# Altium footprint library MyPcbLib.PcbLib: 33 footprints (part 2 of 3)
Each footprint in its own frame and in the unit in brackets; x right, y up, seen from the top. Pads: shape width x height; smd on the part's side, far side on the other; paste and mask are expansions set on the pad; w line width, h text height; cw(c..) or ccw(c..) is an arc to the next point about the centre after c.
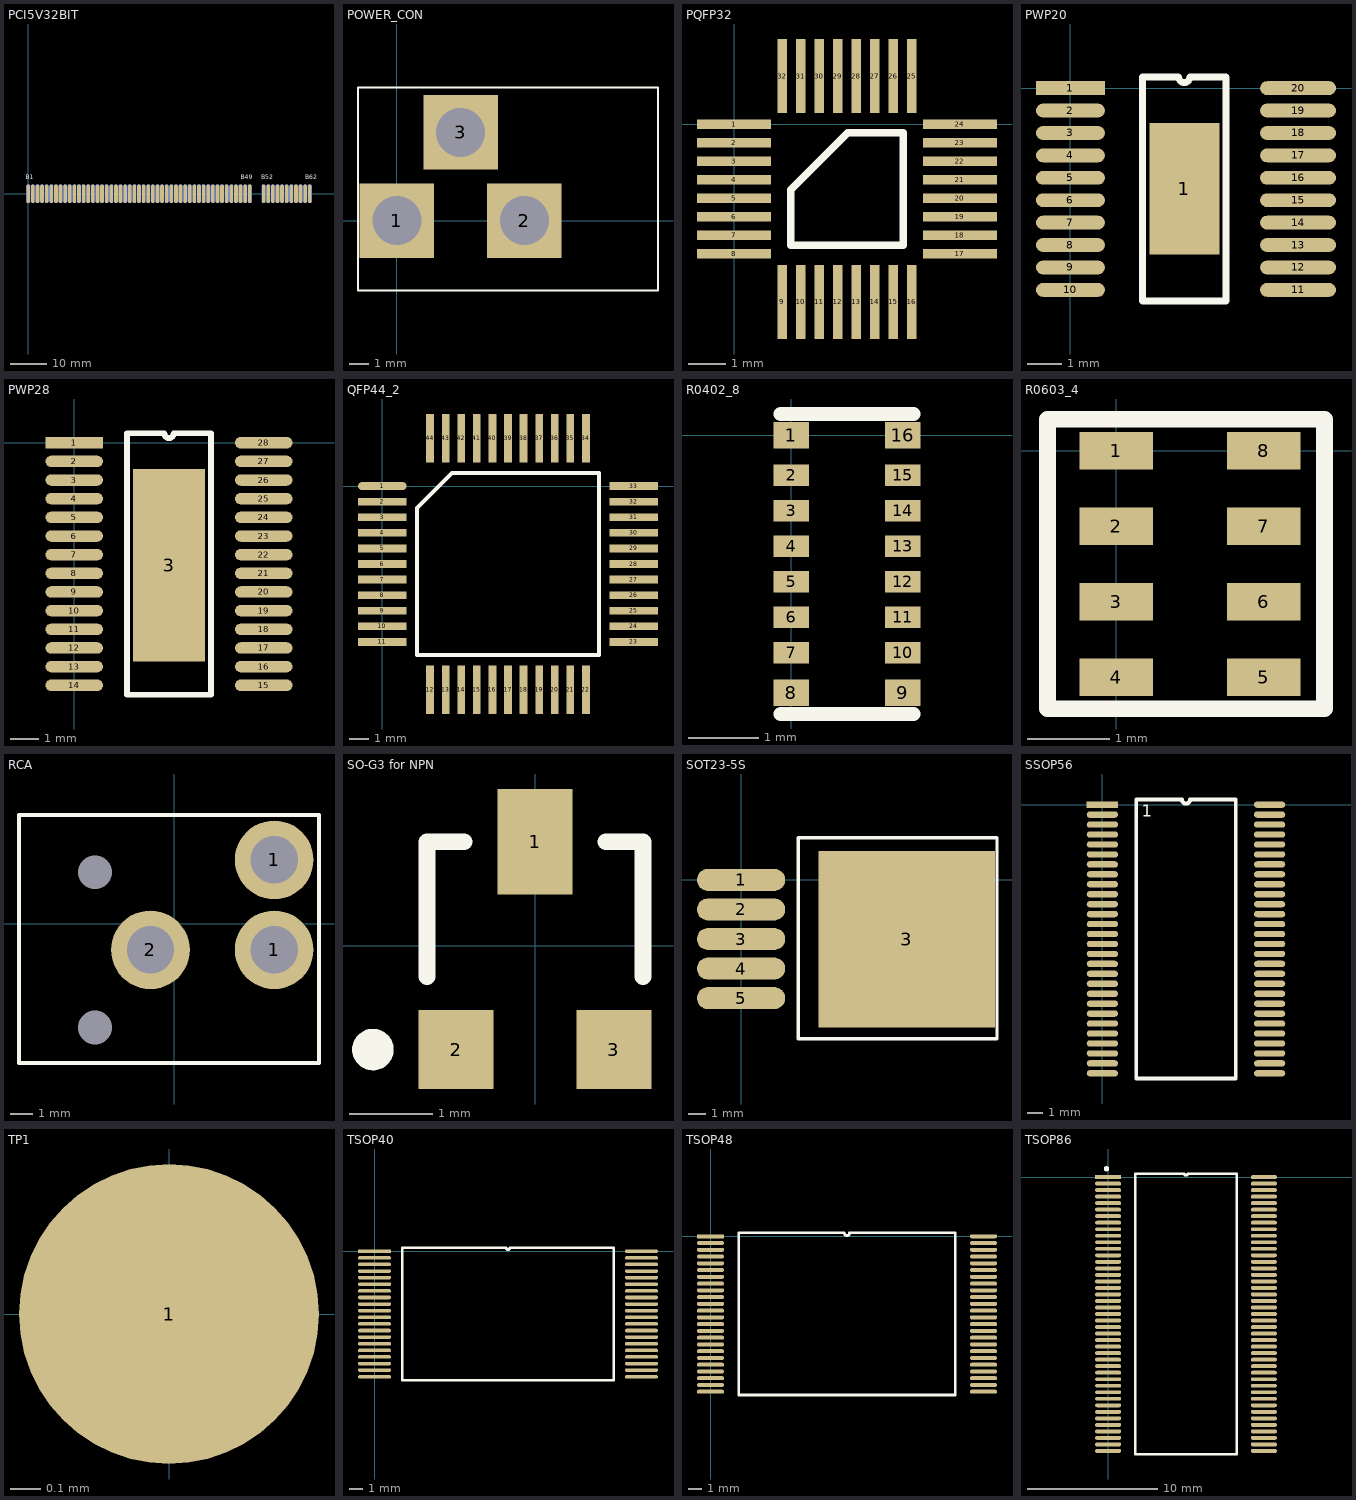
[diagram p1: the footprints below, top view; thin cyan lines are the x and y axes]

## PCI5V32BIT [mil]
pads (120):
  oval 40x200 smd far side: A1(0,0) A2(50,0) A3(100,0) A4(150,0) A5(200,0) A6(250,0) A7(300,0) A8(350,0) A9(400,0) A10(450,0) A11(500,0) A12(550,0) A13(600,0) A14(650,0) A15(700,0) A16(750,0) A17(800,0) A18(850,0) A19(900,0) A20(950,0) A21(1000,0) A22(1050,0) A23(1100,0) A24(1150,0) A25(1200,0) A26(1250,0) A27(1300,0) A28(1350,0) A29(1400,0) A30(1450,0) A31(1500,0) A32(1550,0) A33(1600,0) A34(1650,0) A35(1700,0) A36(1750,0) A37(1800,0) A38(1850,0) A39(1900,0) A40(1950,0) A41(2000,0) A42(2050,0) A43(2100,0) A44(2150,0) A45(2200,0) A46(2250,0) A47(2300,0) A48(2350,0) A49(2400,0) A52(2550,0) A53(2600,0) A54(2650,0) A55(2700,0) A56(2750,0) A57(2800,0) A58(2850,0) A59(2900,0) A60(2950,0) A61(3000,0) A62(3050,0)
  oval 40x200 smd: B1(0,0) B2(50,0) B3(100,0) B4(150,0) B5(200,0) B6(250,0) B7(300,0) B8(350,0) B9(400,0) B10(450,0) B11(500,0) B12(550,0) B13(600,0) B14(650,0) B15(700,0) B16(750,0) B17(800,0) B18(850,0) B19(900,0) B20(950,0) B21(1000,0) B22(1050,0) B23(1100,0) B24(1150,0) B25(1200,0) B26(1250,0) B27(1300,0) B28(1350,0) B29(1400,0) B30(1450,0) B31(1500,0) B32(1550,0) B33(1600,0) B34(1650,0) B35(1700,0) B36(1750,0) B37(1800,0) B38(1850,0) B39(1900,0) B40(1950,0) B41(2000,0) B42(2050,0) B43(2100,0) B44(2150,0) B45(2200,0) B46(2250,0) B47(2300,0) B48(2350,0) B49(2400,0) B52(2550,0) B53(2600,0) B54(2650,0) B55(2700,0) B56(2750,0) B57(2800,0) B58(2850,0) B59(2900,0) B60(2950,0) B61(3000,0) B62(3050,0)
Top Overlay:
  text "B1" at -25,155 h48
  text "B49" at 2300,155 h48
  text "B52" at 2525,155 h48
  text "B62" at 3000,155 h48
Bottom Overlay:
  text "A11" at 525,155 h48
  text "A62" at 3125,155 h48
  text "A14" at 725,155 h48
  text "A1" at 25,155 h48

## POWER_CON [mm] "for power input"
pads (3):
  rect 3.8x3.8 hole 2.5: 1(0,0) 2(6.5,0) 3(3.25,4.5)
Top Overlay:
  lines w0.102: -1.981,-3.556 -1.981,6.782 13.31,6.782 13.31,-3.556 -1.981,-3.556

## PQFP32 [mm] "PQFP32;for TVP5150A"
height 1.05
pads (32):
  rect 2x0.25 smd: 1(0,0) 2(0,-0.5) 3(0,-1) 4(0,-1.5) 5(0,-2) 6(0,-2.5) 7(0,-3) 8(0,-3.5) 17(6.1,-3.5) 18(6.1,-3) 19(6.1,-2.5) 20(6.1,-2) 21(6.1,-1.5) 22(6.1,-1) 23(6.1,-0.5) 24(6.1,0)
  rect 0.25x2 smd: 9(1.3,-4.8) 10(1.8,-4.8) 11(2.3,-4.8) 12(2.8,-4.8) 13(3.3,-4.8) 14(3.8,-4.8) 15(4.3,-4.8) 16(4.8,-4.8) 25(4.8,1.3) 26(4.3,1.3) 27(3.8,1.3) 28(3.3,1.3) 29(2.8,1.3) 30(2.3,1.3) 31(1.8,1.3) 32(1.3,1.3)
Top Overlay:
  lines w0.2: 1.535,-3.265 4.565,-3.265 4.565,-0.235 3.07,-0.235 1.535,-1.77 1.535,-3.265

## PWP20 [mm] "PWP20;PSO;PWP (R-PDSO-G**);for TPS54310"
pads (21):
  rect 2x0.4 smd: 1(0,0)
  rect 2.032x3.81 smd: 1(3.302,-2.921)
  oval 2x0.4 smd: 2(0,-0.65) 3(0,-1.3) 4(0,-1.95) 5(0,-2.6) 6(0,-3.25) 7(0,-3.9) 8(0,-4.55) 9(0,-5.2) 10(0,-5.85)
  oval 2.2x0.4 smd: 11(6.6,-5.85) 12(6.6,-5.2) 13(6.6,-4.55) 14(6.6,-3.9) 15(6.6,-3.25) 16(6.6,-2.6) 17(6.6,-1.95) 18(6.6,-1.3) 19(6.6,-0.65) 20(6.6,0)
Top Overlay:
  lines w0.2: 2.085,-6.175 4.515,-6.175 4.515,0.325 3.462,0.325 cw(c3.3,0.325) 3.137,0.325 2.085,0.325 2.085,-6.175
Top Paste:
  rectangle: 2.286,-4.318 4.318,-1.524

## PWP28 [mm] "PWP28;for TPS767D318"
pads (29):
  rect 2x0.4 smd: 1(0,0)
  oval 2x0.4 smd: 2(0,-0.65) 3(0,-1.3) 4(0,-1.95) 5(0,-2.6) 6(0,-3.25) 7(0,-3.9) 8(0,-4.55) 9(0,-5.2) 10(0,-5.85) 11(0,-6.5) 12(0,-7.15) 13(0,-7.8) 14(0,-8.45) 15(6.6,-8.45) 16(6.6,-7.8) 17(6.6,-7.15) 18(6.6,-6.5) 19(6.6,-5.85) 20(6.6,-5.2) 21(6.6,-4.55) 22(6.6,-3.9) 23(6.6,-3.25) 24(6.6,-2.6) 25(6.6,-1.95) 26(6.6,-1.3) 27(6.6,-0.65) 28(6.6,0)
  rect 2.5x6.7 smd: 3(3.302,-4.267)
Top Overlay:
  lines w0.2: 1.835,-8.775 1.835,0.325 3.137,0.325 ccw(c3.3,0.325) 3.462,0.325 4.765,0.325 4.765,-8.775 1.835,-8.775

## QFP44_2 [mm]
pads (44):
  oval 2.5x0.4 smd: 1(0,0)
  rect 2.5x0.4 smd: 2(0,-0.8) 3(0,-1.6) 4(0,-2.4) 5(0,-3.2) 6(0,-4) 7(0,-4.8) 8(0,-5.6) 9(0,-6.4) 10(0,-7.2) 11(0,-8) 23(12.9,-8) 24(12.9,-7.2) 25(12.9,-6.4) 26(12.9,-5.6) 27(12.9,-4.8) 28(12.9,-4) 29(12.9,-3.2) 30(12.9,-2.4) 31(12.9,-1.6) 32(12.9,-0.8) 33(12.9,0)
  rect 0.4x2.5 smd: 12(2.45,-10.45) 13(3.25,-10.45) 14(4.05,-10.45) 15(4.85,-10.45) 16(5.65,-10.45) 17(6.45,-10.45) 18(7.25,-10.45) 19(8.05,-10.45) 20(8.85,-10.45) 21(9.65,-10.45) 22(10.45,-10.45) 34(10.45,2.45) 35(9.65,2.45) 36(8.85,2.45) 37(8.05,2.45) 38(7.25,2.45) 39(6.45,2.45) 40(5.65,2.45) 41(4.85,2.45) 42(4.05,2.45) 43(3.25,2.45) 44(2.45,2.45)
Top Overlay:
  lines w0.2: 1.785,-8.665 11.115,-8.665 11.115,0.665 3.57,0.665 1.785,-1.12 1.785,-8.665

## R0402_8 [mil]
pads (16):
  rect 20x15 smd: 1(0,0) 8(0,-145) 9(63,-145) 16(63,0)
  rect 20x12 smd: 2(0,-22.5) 3(0,-42.5) 4(0,-62.5) 5(0,-82.5) 6(0,-102.5) 7(0,-122.5) 10(63,-122.5) 11(63,-102.5) 12(63,-82.5) 13(63,-62.5) 14(63,-42.5) 15(63,-22.5)
Top Overlay:
  lines w8: -5.8,-157 69,-157 ; -5.8,12 69,12

## R0603_4 [mil] "for ResPackX4____OK!"
pads (8):
  rect 35x18 smd: 1(0,0) 2(0,-36) 3(0,-72) 4(0,-108) 5(70.16,-108) 6(70.16,-72) 7(70.16,-36) 8(70.16,0)
Top Overlay:
  lines w8: -32.84,15 -32.84,-123 99.16,-123 99.16,15 -31.84,15

## RCA [mm]
pads (5):
  round 3.5 hole 2.1: 1(4.433,-1.168) 1(4.433,2.832) 2(-1.067,-1.168)
  round 0 hole 1.5: 3(-3.53,2.282) 4(-3.53,-4.618)
Top Overlay:
  lines w0.2: -6.909,-6.198 6.426,-6.198 6.426,4.826 -6.909,4.826 -6.909,-6.198

## SO-G3 for NPN [mm]
pads (3):
  rect 0.9x1.27 smd: 1(0,1.25)
  rect 0.9x0.95 smd: 2(-0.95,-1.25) 3(0.95,-1.25)
Top Overlay:
  circle w0.25: c-1.95,-1.25 r0.125
  lines w0.2: -1.3,-0.375 -1.3,1.25 -0.85,1.25 ; 0.85,1.25 1.3,1.25 1.3,-0.375

## SOT23-5S [mil] "for TPS75733"
pads (6):
  oval 200x50 smd: 1(0,0) 2(0,-67) 3(0,-134) 4(0,-201) 5(0,-268)
  rect 400x400 smd: 3(375,-135)
Top Overlay:
  lines w7.87: 130,-360 130,95 580,95 580,-360 130,-360

## SSOP56 [mm] "SSOP56;for CYC68013"
pads (56):
  rect 2x0.4 smd: 1(0,0)
  oval 2x0.4 smd: 2(0,-0.635) 3(0,-1.27) 4(0,-1.905) 5(0,-2.54) 6(0,-3.175) 7(0,-3.81) 8(0,-4.445) 9(0,-5.08) 10(0,-5.715) 11(0,-6.35) 12(0,-6.985) 13(0,-7.62) 14(0,-8.255) 15(0,-8.89) 16(0,-9.525) 17(0,-10.16) 18(0,-10.795) 19(0,-11.43) 20(0,-12.065) 21(0,-12.7) 22(0,-13.335) 23(0,-13.97) 24(0,-14.605) 25(0,-15.24) 26(0,-15.875) 27(0,-16.51) 28(0,-17.145) 29(10.668,-17.145) 30(10.668,-16.51) 31(10.668,-15.875) 32(10.668,-15.24) 33(10.668,-14.605) 34(10.668,-13.97) 35(10.668,-13.335) 36(10.668,-12.7) 37(10.668,-12.065) 38(10.668,-11.43) 39(10.668,-10.795) 40(10.668,-10.16) 41(10.668,-9.525) 42(10.668,-8.89) 43(10.668,-8.255) 44(10.668,-7.62) 45(10.668,-6.985) 46(10.668,-6.35) 47(10.668,-5.715) 48(10.668,-5.08) 49(10.668,-4.445) 50(10.668,-3.81) 51(10.668,-3.175) 52(10.668,-2.54) 53(10.668,-1.905) 54(10.668,-1.27) 55(10.668,-0.635) 56(10.668,0)
Top Overlay:
  lines w0.254: 2.159,-17.462 2.159,0.318 5.08,0.318 ccw(c5.334,0.318) 5.588,0.317 8.509,0.318 8.509,-17.462 2.159,-17.462
  text "1" at 2.515,-0.762 h0.76

## TP1 [mm]
pads (1):
  round 1 smd: 1(0,0)

## TSOP40 [mm] "TSOP40;for Am29LV033C"
height 1.2
pads (40):
  rect 2.5x0.27 smd: 1(0,0)
  oval 2.5x0.27 smd: 2(0,-0.5) 3(0,-1) 4(0,-1.5) 5(0,-2) 6(0,-2.5) 7(0,-3) 8(0,-3.5) 9(0,-4) 10(0,-4.5) 11(0,-5) 12(0,-5.5) 13(0,-6) 14(0,-6.5) 15(0,-7) 16(0,-7.5) 17(0,-8) 18(0,-8.5) 19(0,-9) 20(0,-9.5) 21(20.2,-9.5) 22(20.2,-9) 23(20.2,-8.5) 24(20.2,-8) 25(20.2,-7.5) 26(20.2,-7) 27(20.2,-6.5) 28(20.2,-6) 29(20.2,-5.5) 30(20.2,-5) 31(20.2,-4.5) 32(20.2,-4) 33(20.2,-3.5) 34(20.2,-3) 35(20.2,-2.5) 36(20.2,-2) 37(20.2,-1.5) 38(20.2,-1) 39(20.2,-0.5) 40(20.2,0)
Top Overlay:
  lines w0.2: 2.085,-9.75 18.115,-9.75 18.115,0.25 10.225,0.25 cw(c10.1,0.25) 9.975,0.25 2.085,0.25 2.085,-9.75

## TSOP48 [mm] "for Am29LV800B"
pads (48):
  rect 2x0.3 smd: 1(0,0)
  oval 2x0.3 smd: 2(0,-0.5) 3(0,-1) 4(0,-1.5) 5(0,-2) 6(0,-2.5) 7(0,-3) 8(0,-3.5) 9(0,-4) 10(0,-4.5) 11(0,-5) 12(0,-5.5) 13(0,-6) 14(0,-6.5) 15(0,-7) 16(0,-7.5) 17(0,-8) 18(0,-8.5) 19(0,-9) 20(0,-9.5) 21(0,-10) 22(0,-10.5) 23(0,-11) 24(0,-11.5) 25(20.2,-11.5) 26(20.2,-11) 27(20.2,-10.5) 28(20.2,-10) 29(20.2,-9.5) 30(20.2,-9) 31(20.2,-8.5) 32(20.2,-8) 33(20.2,-7.5) 34(20.2,-7) 35(20.2,-6.5) 36(20.2,-6) 37(20.2,-5.5) 38(20.2,-5) 39(20.2,-4.5) 40(20.2,-4) 41(20.2,-3.5) 42(20.2,-3) 43(20.2,-2.5) 44(20.2,-2) 45(20.2,-1.5) 46(20.2,-1) 47(20.2,-0.5) 48(20.2,0)
Top Overlay:
  lines w0.2: 9.9,0.25 ccw(c10.1,0.25) 10.3,0.25 ; 9.906,0.254 2.085,0.25 2.085,-11.75 18.115,-11.75 18.115,0.25 10.287,0.254

## TSOP86 [mm] "TSOP;43*2;for HY57V283220"
pads (86):
  rect 2x0.3 smd: 1(0,0)
  oval 2x0.3 smd: 2(0,-0.5) 3(0,-1) 4(0,-1.5) 5(0,-2) 6(0,-2.5) 7(0,-3) 8(0,-3.5) 9(0,-4) 10(0,-4.5) 11(0,-5) 12(0,-5.5) 13(0,-6) 14(0,-6.5) 15(0,-7) 16(0,-7.5) 17(0,-8) 18(0,-8.5) 19(0,-9) 20(0,-9.5) 21(0,-10) 22(0,-10.5) 23(0,-11) 24(0,-11.5) 25(0,-12) 26(0,-12.5) 27(0,-13) 28(0,-13.5) 29(0,-14) 30(0,-14.5) 31(0,-15) 32(0,-15.5) 33(0,-16) 34(0,-16.5) 35(0,-17) 36(0,-17.5) 37(0,-18) 38(0,-18.5) 39(0,-19) 40(0,-19.5) 41(0,-20) 42(0,-20.5) 43(0,-21) 44(11.938,-21) 45(11.938,-20.5) 46(11.938,-20) 47(11.938,-19.5) 48(11.938,-19) 49(11.938,-18.5) 50(11.938,-18) 51(11.938,-17.5) 52(11.938,-17) 53(11.938,-16.5) 54(11.938,-16) 55(11.938,-15.5) 56(11.938,-15) 57(11.938,-14.5) 58(11.938,-14) 59(11.938,-13.5) 60(11.938,-13) 61(11.938,-12.5) 62(11.938,-12) 63(11.938,-11.5) 64(11.938,-11) 65(11.938,-10.5) 66(11.938,-10) 67(11.938,-9.5) 68(11.938,-9) 69(11.938,-8.5) 70(11.938,-8) 71(11.938,-7.5) 72(11.938,-7) 73(11.938,-6.5) 74(11.938,-6) 75(11.938,-5.5) 76(11.938,-5) 77(11.938,-4.5) 78(11.938,-4) 79(11.938,-3.5) 80(11.938,-3) 81(11.938,-2.5) 82(11.938,-2) 83(11.938,-1.5) 84(11.938,-1) 85(11.938,-0.5) 86(11.938,0)
Top Overlay:
  circle w0.2: c-0.125,0.635 r0.1
  lines w0.2: 2.085,-21.25 9.853,-21.25 9.853,0.25 6.094,0.25 cw(c5.969,0.25) 5.844,0.25 2.085,0.25 2.085,-21.25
